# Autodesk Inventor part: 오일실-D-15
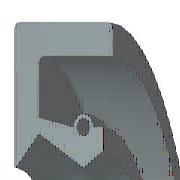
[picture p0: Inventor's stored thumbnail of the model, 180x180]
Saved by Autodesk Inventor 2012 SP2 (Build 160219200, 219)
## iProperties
IsCustomPart: 0
Company: 한국ATC센터
Created: 2014-12
Part Number: 오일실-D-15
Material: 고무
Description: 오일-실
Document SubType Name: Modeling
Standard: KS B 2804
Designer: KYOUNG IL JANG
Standards Organization: KS
Language: ko-KR
Size Designation: D - 15 30 7
Categories: <MemberInstance><Categories><Category DisplayName="샤프트 부품" InternalName="7f7aeb1f-a693-4053-b835-cee3144e0d98" Mnemonic="SHFT"><Category DisplayName="실링" Intern
Density: 0.93 g/cm^3
Mass: 1.95008 g
Surface Area: 27.8517 cm^2
Volume: 2.09686 cm^3
Author: KYOUNG IL JANG
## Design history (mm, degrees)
revolve "본체" stored, may be unused: angle "d17" = 90 deg
revolve "스프링1" stored, may be unused: angle "d18" = 90 deg
body "Solid1"
sketch "스케치1"
  geometry: L1 (0, 15)-(7, 15); L2 (7, 13.25)-(1.75, 13.25); L3 (1.75, 9.25)-(4.9, 7.5); L4 (4.9, 7.5)-(0, 7.5); L5 (0, 0)-(9.586, 0) reference; L6 (4.9, 7.5)-(6.3, 8.375); L7 (0, 18)-(0, -3) reference; L8 (-1.941, 0)-(11.507, 0) reference; L9 (4.2, 9.6)-(1.75, 10.09); L10 (1.75, 10.09)-(1.75, 13.25); L11 (0, 15)-(0, 7.588); L12 (4.9, 7.5)-(0, 7.5); L13 (1.75, 9.25)-(0.152, 7.528); L14 (7, 15)-(7, 13.25); L15 (5.6, 9.6)-(6.3, 9.6); L16 (6.3, 9.6)-(6.3, 8.375); C1 r 0.455 at (4.9, 9.6); A1 r 0.7 centre (4.9, 9.6) between (5.6, 9.6) and (4.2, 9.6); A2 r 0.088 centre (0.088, 7.588) between (0, 7.588) and (0.152, 7.528); 1 further point
  constraints: 28 end point, 5 horizontal alignment, 5 point on line, 4 point on circle, 4 vertical alignment, 3 centre point, 3 tangent, 2 collinear, 2 horizontal, 2 perpendicular, 1 coincident, 1 parallel
  dimensions: "d0" = 30 diameter of L1 L5 (= SD2); "d1" = 1.75 distance of L1.end L2.start (= SD); "d2" = 0.91 diameter of C1 (= SPDI); "d3" = 1.4 diameter of A1 (= SPDA); "d4" = 15 diameter of L3.end L5 (= NND); "d5" = 18.5 diameter of L3.start L5 (= TKDM); "d7" = 20.18 diameter of L9.end L5 (= TKDM + 0.24 x SWDT); "d8" = 1.75 distance between parallel lines of L11 L10 (= SD); "d9" = 4.9 distance from line of L11 C1.centre (= SPDST); "d10" = 19.2 diameter of C1.centre L5 (= HLDM); "d11" = 0.0875 radius of A2 (= 0.25 x LAB); "d12" = 6.3 distance between parallel lines of L11 L16 (= SDI); "d13" = 16.75 diameter of L6.end L5 (= ABDM); "d14" = 7 distance from line of L11 L1.end (= SWDT)
fillet "모깎기1" dims "d6" = 0.3 (= RR)
other parameters: "SD2" = 30 [user parameter; used in 1 equation term], "SWDT" = 7 [user parameter; used in 2 equation terms], "RR" = 0.3 [user parameter; used in 1 equation term], "SD" = 1.75 [user parameter; used in 2 equation terms], "NND" = 15 [user parameter; used in 1 equation term], "SPDA" = 1.4 [user parameter; used in 1 equation term], "SPDI" = 0.91 [user parameter; used in 1 equation term], "TKDM" = 18.5 [user parameter; used in 2 equation terms], "HLDM" = 19.2 [user parameter; used in 1 equation term], "ABDM" = 16.75 [user parameter; used in 1 equation term], "SDI" = 6.3 [user parameter; used in 1 equation term], "SPDST" = 4.9 [user parameter; used in 1 equation term], "LAB" = 0.35 [user parameter; used in 1 equation term], "d15" = 0, "d16" = 0, "d19" = 0
